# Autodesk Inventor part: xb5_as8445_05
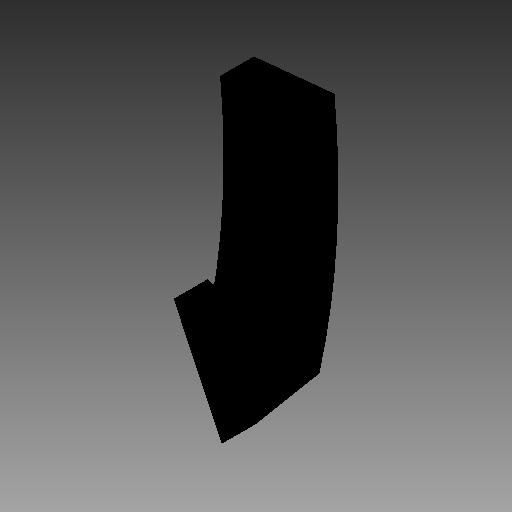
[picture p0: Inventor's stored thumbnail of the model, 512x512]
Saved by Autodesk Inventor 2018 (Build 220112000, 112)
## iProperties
Company: TraceParts S.A.
Created: 2018-04
Part Number: xb5_as8445_05
Checked By: TraceParts S.A.
Material: Generic
Catalog Web Link: www.traceparts.com
Document SubType Name: Modeling
Designer: TraceParts
Density: 1 g/cm^3
Appearance: Default
Author: TraceParts
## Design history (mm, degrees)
feature "xb5_as8445_05.ipt"
body "Solid1"
